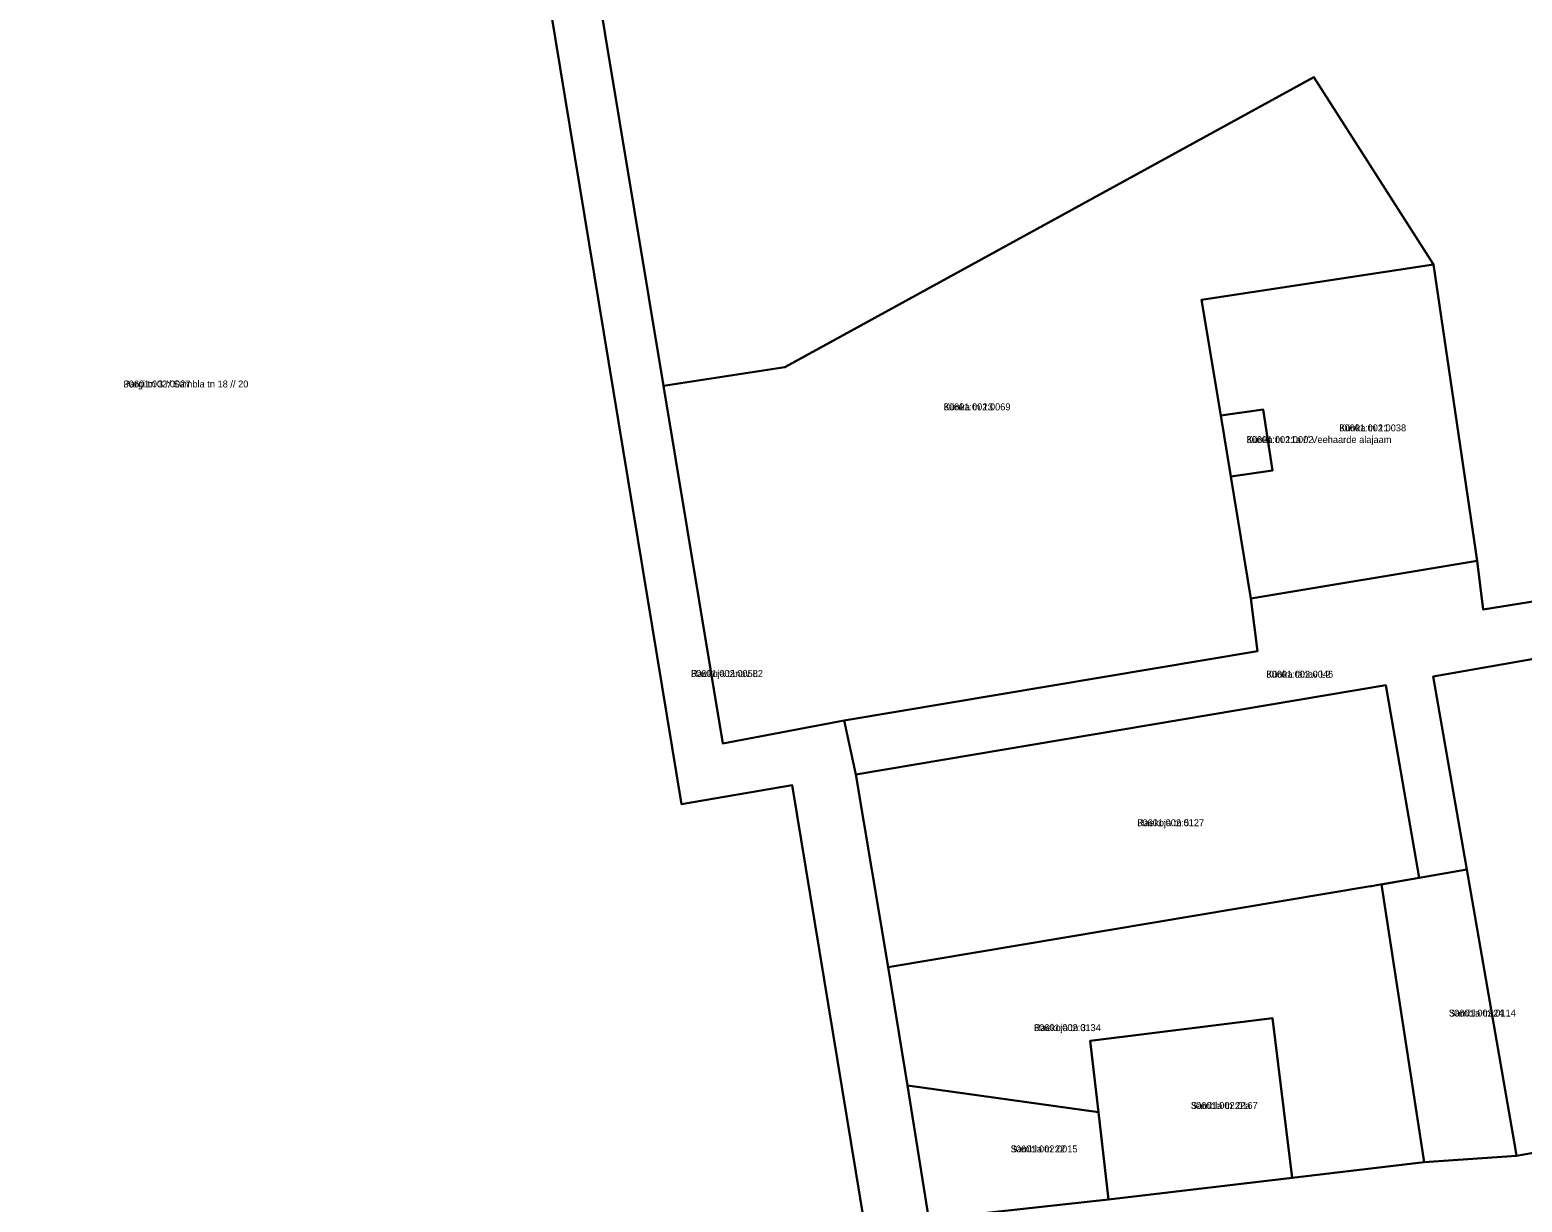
# Model space of a CAD drawing. Extents: x 534470 to 574598, y 6422978 to 6468590.
# Drawn here: x 556053.8 to 556377.6, y 6445906.5 to 6446160.9 of the extents above; entities that cross this region are included whole.
import ezdxf

# ---------------------------------------------------------------- set-up
doc = ezdxf.new("R2010")
doc.units = 0
for name, color, linetype in [('L_AADRESS', 7, 'Continuous'), ('PIIR', 7, 'Continuous'), ('TUNNUS', 7, 'Continuous')]:
    doc.layers.add(name, color=color, linetype=linetype)

msp = doc.modelspace()

# ---------------------------------------------------------------- linework, layer by layer
at = {"layer": 'PIIR'}
for points in [[(556662.13, 6446380.06), (556713.3, 6446102.07), (556714.41, 6446096.17), (556717.2, 6446081), (556619.92, 6446063.7), (556498.18, 6446045.02), (556487.23, 6446054.07), (556369.2, 6446035.09), (556367.86, 6446045.65), (556358.4, 6446109.93), (556332.42, 6446150.63), (556217.63, 6446087.67), (556191.28, 6446083.63), (556156.17, 6446294.94)], [(555926.11, 6446052.54), (555913.23, 6446058.68), (555951.55, 6446135.9), (555935.37, 6446256.23), (556145.61, 6446293.62), (556195.16, 6445992.83), (556219.21, 6445996.95), (556234.96, 6445901.25), (555966, 6445875.18), (555945.25, 6446003.51), (555934.49, 6446003.24)], [(556156.17, 6446294.94), (556191.28, 6446083.63), (556204.18, 6446006.01), (556230.48, 6446011.03), (556233.02, 6445999.31), (556240.04, 6445957.49), (556244.23, 6445931.83), (556248.88, 6445902.78), (556234.96, 6445901.25), (556219.21, 6445996.95), (556195.16, 6445992.83), (556145.61, 6446293.62)], [(556332.42, 6446150.63), (556358.4, 6446109.93), (556308.05, 6446102.31), (556312.2, 6446077.16), (556314.37, 6446063.97), (556318.74, 6446037.47), (556320.16, 6446026.05), (556230.48, 6446011.03), (556204.18, 6446006.01), (556191.28, 6446083.63), (556217.63, 6446087.67)], [(556308.05, 6446102.31), (556358.4, 6446109.93), (556367.86, 6446045.65), (556318.74, 6446037.47), (556314.37, 6446063.97), (556323.43, 6446065.26), (556321.41, 6446078.48), (556312.2, 6446077.16)], [(556314.37, 6446063.97), (556312.2, 6446077.16), (556321.41, 6446078.48), (556323.43, 6446065.26)], [(556376.4, 6445916.55), (556376.19, 6445917.92), (556365.62, 6445978.67), (556358.33, 6446020.55), (556396.63, 6446027.29), (556403.24, 6445987.84), (556414.06, 6445923.27)], [(556240.04, 6445957.49), (556233.02, 6445999.31), (556348.02, 6446018.67), (556355.25, 6445976.91), (556346.03, 6445975.28), (556344.97, 6445975.1), (556344.75, 6445975.07)], [(556347.1, 6445975.46), (556355.25, 6445976.91), (556365.62, 6445978.67), (556376.19, 6445917.92), (556376.4, 6445916.55), (556356.35, 6445915.18)], [(556240.04, 6445957.49), (556344.75, 6445975.07), (556344.97, 6445975.1), (556346.03, 6445975.28), (556347.1, 6445975.46), (556356.35, 6445915.18), (556327.74, 6445911.79), (556323.47, 6445946.39), (556283.88, 6445941.5), (556285.68, 6445926), (556244.23, 6445931.83)], [(556287.89, 6445907.07), (556285.68, 6445926), (556283.88, 6445941.5), (556323.47, 6445946.39), (556327.74, 6445911.79)], [(556244.23, 6445931.83), (556285.68, 6445926), (556287.89, 6445907.07), (556248.88, 6445902.78)]]:
    msp.add_lwpolyline(points, close=True, dxfattribs=at)
for points in [[(556396.63, 6446027.29), (556358.33, 6446020.55), (556365.62, 6445978.67), (556355.25, 6445976.91), (556348.02, 6446018.67), (556233.02, 6445999.31), (556230.48, 6446011.03), (556320.16, 6446026.05), (556318.74, 6446037.47), (556367.86, 6446045.65), (556369.2, 6446035.09), (556487.23, 6446054.07)], [(555966, 6445875.18), (556234.96, 6445901.25), (556248.88, 6445902.78), (556287.89, 6445907.07), (556327.74, 6445911.79), (556356.35, 6445915.18), (556376.4, 6445916.55), (556414.06, 6445923.27), (556451.67, 6445929.6), (556491.57, 6445936.41), (556491.8, 6445935.34), (556510.74, 6445939.71), (556547.71, 6445946), (556565.37, 6445949.33), (556593.79, 6445954.32), (556624.35, 6445959.68), (556660.08, 6445965.95), (556682.28, 6445969.85)]]:
    msp.add_lwpolyline(points, dxfattribs=at)

# ---------------------------------------------------------------- texts
at = {"layer": 'L_AADRESS'}
for s, p in [('Pargi tn 3 // Sambla tn 18 // 20', (556074.09, 6446083.28)), ('Künka tn 13', (556252.09, 6446078.32)), ('Künka tn 11a // Veehaarde alajaam', (556317.82, 6446071.21)), ('Künka tn 11', (556337.95, 6446073.75)), ('Raekoja tänav L2', (556197.25, 6446020.46)), ('Künka tänav L2', (556322.12, 6446020.3)), ('Raekoja tn 5', (556294.11, 6445988.08)), ('Sambla tn 24', (556361.75, 6445946.78)), ('Raekoja tn 3', (556271.69, 6445943.62)), ('Sambla tn 22a', (556305.75, 6445926.73)), ('Sambla tn 22', (556266.63, 6445917.3))]:
    msp.add_text(s, height=1.5, dxfattribs=at).set_placement(p)
at = {"layer": 'TUNNUS'}
for s, p in [('30601:002:0027', (556074.09, 6446083.28)), ('30601:002:0069', (556252.09, 6446078.32)), ('30601:002:0002', (556317.82, 6446071.21)), ('30601:002:0038', (556337.95, 6446073.75)), ('30601:002:0058', (556197.25, 6446020.46)), ('30601:002:0046', (556322.12, 6446020.3)), ('30601:002:0127', (556294.11, 6445988.08)), ('30601:002:0114', (556361.75, 6445946.78)), ('30601:002:0134', (556271.69, 6445943.62)), ('30601:002:0167', (556305.75, 6445926.73)), ('30601:002:0015', (556266.63, 6445917.3))]:
    msp.add_text(s, height=1.5, dxfattribs=at).set_placement(p)

doc.saveas('drawing.dxf')
